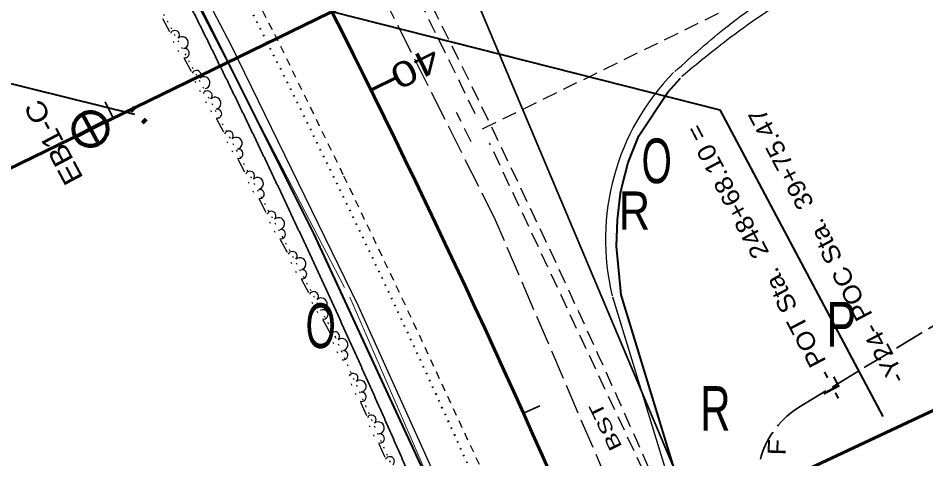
# Model space of a CAD drawing. Extents: x 2402199 to 2404507, y 568050 to 571478.
# Drawn here: x 2402420.4 to 2402674.4, y 570872 to 570995.3 of the extents above; entities that cross this region are included whole.
import ezdxf
from ezdxf.enums import TextEntityAlignment as Align

# ---------------------------------------------------------------- set-up
doc = ezdxf.new("R2010")
doc.units = 0
doc.header["$LTSCALE"] = 1.4
for name, pattern in [('DOTTED', [1.5, 0.3, -1.2]), ('LONG_DASHED', [7.5, 6, -1.5]), ('MEDIUM_DASHED', [4.5, 3, -1.5]), ('SHORT_DASHED', [2.7, 1.5, -1.2])]:
    doc.linetypes.add(name, pattern=pattern)
for name, color, linetype, lineweight in [('1', 7, 'Continuous', 35), ('11', 7, 'Continuous', 25), ('15', 7, 'DOTTED', 40), ('17', 7, 'MEDIUM_DASHED', 35), ('18', 7, 'SHORT_DASHED', 25), ('19', 7, 'Continuous', 35), ('21', 7, 'Continuous', 40), ('27', 7, 'Continuous', 80), ('28', 7, 'Continuous', 25), ('3', 7, 'Continuous', 25), ('42', 7, 'Continuous', 25), ('6', 7, 'Continuous', 35), ('62', 7, 'Continuous', 60), ('63', 7, 'Continuous', 35), ('9', 7, 'Continuous', 13)]:
    doc.layers.add(name, color=color, linetype=linetype, lineweight=lineweight)
for name, color, linetype in [('14', 7, 'Continuous'), ('2', 7, 'Continuous'), ('23', 7, 'Continuous')]:
    doc.layers.add(name, color=color, linetype=linetype)

msp = doc.modelspace()

# ---------------------------------------------------------------- linework, layer by layer
at = {"layer": '1'}
msp.add_line((2402526.719, 571052.414), (2402605.967, 570864.37), dxfattribs=at)
for points in [[(2402475.474, 570984.701), (2402475.081, 570985.499), (2402474.689, 570986.297), (2402474.296, 570987.095), (2402473.903, 570987.893), (2402473.51, 570988.691), (2402473.112, 570989.497), (2402472.718, 570990.294), (2402472.325, 570991.091), (2402471.93, 570991.889), (2402471.536, 570992.685), (2402471.141, 570993.482), (2402470.746, 570994.279), (2402470.351, 570995.076), (2402469.956, 570995.872), (2402469.56, 570996.669), (2402469.164, 570997.465), (2402468.763, 570998.27), (2402468.367, 570999.066), (2402467.97, 570999.861), (2402467.573, 571000.657), (2402467.176, 571001.453), (2402466.779, 571002.249), (2402466.381, 571003.044), (2402465.983, 571003.84), (2402465.585, 571004.634), (2402465.186, 571005.429), (2402464.788, 571006.225), (2402464.385, 571007.028), (2402463.985, 571007.823), (2402463.586, 571008.618), (2402463.186, 571009.412), (2402462.786, 571010.206), (2402462.386, 571011), (2402461.985, 571011.794), (2402461.585, 571012.589), (2402461.184, 571013.382), (2402460.783, 571014.176), (2402460.382, 571014.969), (2402459.975, 571015.772), (2402459.573, 571016.565), (2402459.171, 571017.358), (2402458.769, 571018.152), (2402458.366, 571018.944), (2402457.963, 571019.737), (2402457.56, 571020.53), (2402457.157, 571021.323), (2402456.753, 571022.115), (2402456.349, 571022.907), (2402455.945, 571023.699), (2402455.536, 571024.5), (2402455.131, 571025.293), (2402454.726, 571026.084), (2402454.321, 571026.876), (2402453.916, 571027.668), (2402453.51, 571028.459), (2402453.104, 571029.251), (2402452.698, 571030.042), (2402452.291, 571030.833), (2402451.885, 571031.624), (2402451.478, 571032.415), (2402451.071, 571033.206), (2402450.659, 571034.005), (2402450.251, 571034.796), (2402449.843, 571035.586), (2402449.435, 571036.376), (2402449.027, 571037.167), (2402448.618, 571037.956), (2402448.209, 571038.746), (2402447.8, 571039.536), (2402447.39, 571040.326), (2402446.981, 571041.116), (2402446.571, 571041.904), (2402446.157, 571042.703), (2402445.746, 571043.492)], [(2402503.828, 570925.255), (2402503.454, 570926.062), (2402503.076, 570926.878), (2402502.703, 570927.684), (2402502.328, 570928.491), (2402501.954, 570929.297), (2402501.579, 570930.103), (2402501.203, 570930.909), (2402500.828, 570931.715), (2402500.453, 570932.521), (2402500.077, 570933.327), (2402499.701, 570934.132), (2402499.325, 570934.937), (2402498.944, 570935.752), (2402498.567, 570936.557), (2402498.19, 570937.362), (2402497.812, 570938.167), (2402497.435, 570938.972), (2402497.057, 570939.777), (2402496.679, 570940.581), (2402496.3, 570941.386), (2402495.922, 570942.191), (2402495.543, 570942.994), (2402495.164, 570943.799), (2402494.785, 570944.603), (2402494.4, 570945.416), (2402494.021, 570946.22), (2402493.641, 570947.023), (2402493.26, 570947.827), (2402492.88, 570948.63), (2402492.499, 570949.434), (2402492.118, 570950.237), (2402491.736, 570951.04), (2402491.354, 570951.843), (2402490.973, 570952.646), (2402490.591, 570953.449), (2402490.204, 570954.26), (2402489.821, 570955.063), (2402489.438, 570955.865), (2402489.055, 570956.667), (2402488.672, 570957.47), (2402488.288, 570958.272), (2402487.904, 570959.074), (2402487.52, 570959.876), (2402487.136, 570960.677), (2402486.751, 570961.479), (2402486.366, 570962.28), (2402485.977, 570963.091), (2402485.591, 570963.892), (2402485.206, 570964.694), (2402484.82, 570965.494), (2402484.433, 570966.295), (2402484.047, 570967.096), (2402483.661, 570967.897), (2402483.274, 570968.697), (2402482.887, 570969.498), (2402482.499, 570970.298), (2402482.111, 570971.098), (2402481.719, 570971.907), (2402481.331, 570972.707), (2402480.942, 570973.507), (2402480.554, 570974.307), (2402480.165, 570975.106), (2402479.775, 570975.905), (2402479.386, 570976.706), (2402478.996, 570977.505), (2402478.606, 570978.304), (2402478.216, 570979.103), (2402477.826, 570979.901), (2402477.431, 570980.709), (2402477.04, 570981.508), (2402476.649, 570982.306), (2402476.257, 570983.105), (2402475.865, 570983.903), (2402475.473, 570984.702)], [(2402530.791, 570865.196), (2402530.436, 570866.011), (2402530.081, 570866.826), (2402529.726, 570867.64), (2402529.371, 570868.455), (2402529.015, 570869.269), (2402528.659, 570870.084), (2402528.303, 570870.898), (2402527.946, 570871.712), (2402527.589, 570872.526), (2402527.228, 570873.349), (2402526.871, 570874.163), (2402526.513, 570874.976), (2402526.155, 570875.791), (2402525.798, 570876.603), (2402525.439, 570877.417), (2402525.081, 570878.23), (2402524.722, 570879.043), (2402524.363, 570879.856), (2402524.004, 570880.669), (2402523.644, 570881.482), (2402523.28, 570882.304), (2402522.92, 570883.117), (2402522.56, 570883.929), (2402522.199, 570884.742), (2402521.838, 570885.554), (2402521.477, 570886.366), (2402521.115, 570887.178), (2402520.754, 570887.99), (2402520.392, 570888.802), (2402520.03, 570889.613), (2402519.668, 570890.425), (2402519.301, 570891.246), (2402518.938, 570892.057), (2402518.575, 570892.868), (2402518.212, 570893.679), (2402517.848, 570894.491), (2402517.484, 570895.302), (2402517.12, 570896.113), (2402516.755, 570896.924), (2402516.391, 570897.734), (2402516.026, 570898.544), (2402515.661, 570899.355), (2402515.291, 570900.174), (2402514.925, 570900.984), (2402514.559, 570901.794), (2402514.193, 570902.604), (2402513.827, 570903.414), (2402513.46, 570904.223), (2402513.093, 570905.034), (2402512.726, 570905.843), (2402512.358, 570906.652), (2402511.99, 570907.462), (2402511.623, 570908.271), (2402511.251, 570909.089), (2402510.882, 570909.898), (2402510.513, 570910.707), (2402510.144, 570911.515), (2402509.775, 570912.324), (2402509.405, 570913.132), (2402509.035, 570913.941), (2402508.666, 570914.749), (2402508.295, 570915.557), (2402507.925, 570916.366), (2402507.554, 570917.173), (2402507.179, 570917.99), (2402506.807, 570918.798), (2402506.436, 570919.606), (2402506.064, 570920.413), (2402505.692, 570921.22), (2402505.32, 570922.028), (2402504.947, 570922.835), (2402504.575, 570923.642), (2402504.201, 570924.449), (2402503.828, 570925.256)]]:
    msp.add_spline(points, degree=3, dxfattribs=at)
at = {"layer": '11'}
for p, q in [((2402460.745, 570995.182), (2402462.697, 570991.575)), ((2402463.703, 570988.856), (2402463.899, 570988.495)), ((2402465.07, 570986.33), (2402465.265, 570985.97)), ((2402466.798, 570984.002), (2402468.75, 570980.395)), ((2402469.757, 570977.676), (2402469.952, 570977.315)), ((2402471.123, 570975.151), (2402471.319, 570974.791)), ((2402472.815, 570971.97), (2402473.007, 570971.607)), ((2402474.161, 570969.431), (2402474.353, 570969.069)), ((2402475.866, 570967.088), (2402477.785, 570963.464)), ((2402478.766, 570960.735), (2402478.958, 570960.373)), ((2402480.11, 570958.199), (2402480.302, 570957.836)), ((2402481.816, 570955.853), (2402483.735, 570952.23)), ((2402484.717, 570949.501), (2402484.908, 570949.139)), ((2402486.061, 570946.964), (2402486.253, 570946.601)), ((2402487.767, 570944.619), (2402489.686, 570940.995)), ((2402490.668, 570938.265), (2402490.86, 570937.903)), ((2402492.012, 570935.728), (2402492.204, 570935.366)), ((2402493.717, 570933.385), (2402495.637, 570929.76)), ((2402496.618, 570927.031), (2402496.81, 570926.669)), ((2402497.962, 570924.495), (2402498.154, 570924.132)), ((2402499.668, 570922.15), (2402501.587, 570918.526)), ((2402502.568, 570915.797), (2402502.76, 570915.434)), ((2402503.913, 570913.26), (2402504.104, 570912.897)), ((2402505.619, 570910.915), (2402507.538, 570907.292)), ((2402508.407, 570904.608), (2402508.572, 570904.233)), ((2402509.557, 570901.978), (2402509.722, 570901.603)), ((2402513.502, 570892.965), (2402513.666, 570892.588)), ((2402514.653, 570890.334), (2402514.817, 570889.958)), ((2402516.18, 570887.867), (2402517.824, 570884.11)), ((2402518.599, 570881.314), (2402518.764, 570880.938)), ((2402519.75, 570878.684), (2402519.915, 570878.309)), ((2402521.277, 570876.22), (2402522.921, 570872.463))]:
    msp.add_line(p, q, dxfattribs=at)
at = {"layer": '11', "linetype": 'DOTTED'}
for points in [[(2402402.474, 571095.885), (2402413.129, 571099.725), (2402421.048, 571070.224), (2402472.559, 570975.083)], [(2402472.559, 570975.083), (2402509.097, 570906.101), (2402545.728, 570822.387)]]:
    msp.add_lwpolyline(points, dxfattribs=at)
at = {"layer": '11'}
for centre, radius, start, end in [((2402464.2, 570990.523), 1.297, 316.86691, 157.66348), ((2402466.288, 570988.389), 1.691, 284.39572, 132.46821), ((2402466.933, 570985.474), 1.297, 259.20044, 99.99701), ((2402470.253, 570979.343), 1.297, 316.86691, 157.66348), ((2402472.341, 570977.209), 1.691, 284.39572, 132.46821), ((2402473.327, 570973.633), 1.297, 316.34386, 157.14043), ((2402475.396, 570971.48), 1.691, 283.87267, 131.94516), ((2402476.015, 570968.559), 1.297, 258.67739, 99.47396), ((2402479.278, 570962.398), 1.297, 316.34386, 157.14043), ((2402481.346, 570960.245), 1.691, 283.87267, 131.94516), ((2402481.965, 570957.325), 1.297, 258.67739, 99.47396), ((2402485.228, 570951.164), 1.297, 316.34386, 157.14043), ((2402487.297, 570949.011), 1.691, 283.87267, 131.94516), ((2402487.916, 570946.09), 1.297, 258.67739, 99.47396), ((2402491.179, 570939.929), 1.297, 316.34386, 157.14043), ((2402493.248, 570937.776), 1.691, 283.87267, 131.94516), ((2402493.867, 570934.855), 1.297, 258.67739, 99.47396), ((2402497.13, 570928.694), 1.297, 316.34386, 157.14043), ((2402499.198, 570926.542), 1.691, 283.87267, 131.94516), ((2402499.817, 570923.621), 1.297, 258.67739, 99.47396), ((2402503.08, 570917.46), 1.297, 316.34386, 157.14043), ((2402505.149, 570915.307), 1.691, 283.87267, 131.94516), ((2402505.768, 570912.386), 1.297, 258.67739, 99.47396), ((2402509.031, 570906.225), 1.297, 316.34386, 157.14043), ((2402510.943, 570903.929), 1.691, 279.59664, 127.66913), ((2402511.342, 570900.97), 1.297, 254.40136, 95.19793), ((2402514.137, 570894.583), 1.297, 312.06783, 152.8644), ((2402516.039, 570892.282), 1.691, 279.59664, 127.66913), ((2402516.439, 570889.323), 1.297, 254.40136, 95.19793), ((2402519.233, 570882.936), 1.297, 312.06783, 152.8644), ((2402521.136, 570880.635), 1.691, 279.59664, 127.66913), ((2402521.535, 570877.676), 1.297, 254.40136, 95.19793), ((2402524.33, 570871.289), 1.297, 312.06783, 152.8644)]:
    msp.add_arc(centre, radius, start, end, dxfattribs=at)
at = {"layer": '15'}
msp.add_arc((2399911.332, 569690.208), 2887.133, 22.84472, 37.57762, dxfattribs=at)
at = {"layer": '17', "lineweight": 25}
for p, q in [((2402548.257, 570968.542), (2402505.556, 571055.624)), ((2402550.332, 570964.289), (2402655.74, 571015.937)), ((2402547.099, 570960.663), (2402543.057, 570968.914)), ((2402616.8, 570822.931), (2402552.299, 570960.292))]:
    msp.add_line(p, q, dxfattribs=at)
at = {"layer": '17', "linetype": 'LONG_DASHED'}
msp.add_line((2402639.183, 570886.623), (2402692.803, 570919.098), dxfattribs=at)
at = {"layer": '17', "linetype": 'Continuous', "lineweight": 60}
msp.add_line((2402707.695, 570900.235), (2402626.394, 570862.088), dxfattribs=at)
at = {"layer": '17', "lineweight": 25}
msp.add_arc((2399953.615, 569708.021), 2887.133, 22.84472, 31.18511, dxfattribs=at)
at = {"layer": '17', "linetype": 'LONG_DASHED'}
msp.add_arc((2402652.134, 570865.24), 25, 121.20094, 203.74382, dxfattribs=at)
at = {"layer": '18'}
msp.add_lwpolyline([(2402476.431, 571020.802), (2402492.105, 570990.812), (2402511.433, 570951.178), (2402527.751, 570916.956), (2402550.218, 570868.56), (2402584.143, 570790.967), (2402591.502, 570773.916)], dxfattribs=at)
at = {"layer": '19', "linetype": 'LONG_DASHED', "lineweight": 25}
msp.add_line((2402618.477, 570788.259), (2402553.966, 570938.719), dxfattribs=at)
msp.add_lwpolyline([(2402553.96, 570938.781), (2402489.547, 571067.152), (2402430.056, 571174.439), (2402385.495, 571247.202)], dxfattribs=at)
at = {"layer": '21'}
msp.add_line((2402453.011, 570968.339), (2402374.495, 570987.785), dxfattribs=at)
for points in [[(2402571.932, 570780.533), (2402538.299, 570859.007), (2402503.143, 570934.851), (2402464.804, 571011.777), (2402426.113, 571084.024), (2402384.214, 571156.832), (2402372.534, 571175.865)], [(2402605.193, 570865.012), (2402589.054, 570917.907), (2402587.809, 570931.49), (2402588.036, 570938.82), (2402588.896, 570946.33), (2402589.348, 570948.395), (2402591.028, 570954.851), (2402594.052, 570962.351), (2402602.158, 570974.597), (2402605.678, 570978.446)]]:
    msp.add_lwpolyline(points, dxfattribs=at)
at = {"layer": '27'}
for p, q in [((2402438.377, 570968.442), (2402442.831, 570960.066)), ((2402444.792, 570966.481), (2402436.416, 570962.029)), ((2402436.391, 570962.075), (2402436.416, 570962.029))]:
    msp.add_line(p, q, dxfattribs=at)
for points in [[(2402444.792, 570966.481), (2402440.604, 570964.255), (2402438.377, 570968.442), (2402438.331, 570968.417)], [(2402436.416, 570962.029), (2402440.604, 570964.255), (2402442.831, 570960.066)]]:
    msp.add_lwpolyline(points, dxfattribs=at)
msp.add_circle((2402440.604, 570964.255), 4.743, dxfattribs=at)
for start, end in [(28, 118.64427), (207.35574, 298)]:
    msp.add_arc((2402440.604, 570964.255), 4.743, start, end, dxfattribs=at)
at = {"layer": '28'}
msp.add_line((2402603.145, 570863.853), (2402586.729, 570917.175), dxfattribs=at)
msp.add_lwpolyline([(2402374.812, 571177.076), (2402399.705, 571135.603), (2402440.232, 571063.522), (2402479.967, 570987.625), (2402515.512, 570914.776), (2402552.113, 570833.795), (2402574.37, 570781.072)], dxfattribs=at)
msp.add_ellipse((2402651.713, 570933.349), major_axis=(-45.019, -49.609), ratio=0.999993, start_param=4.6772796, end_param=5.6872778, dxfattribs=at)
msp.add_spline([(2402672.797, 571021.249), (2402662.311, 571016.13), (2402638.421, 571002.609), (2402618.59, 570989.004), (2402606.097, 570978.965)], degree=3, dxfattribs=at)
at = {"layer": '3', "lineweight": 35}
msp.add_line((2402526.719, 571052.414), (2402619.911, 570831.283), dxfattribs=at)
at = {"layer": '3'}
msp.add_line((2402603.38, 570863.206), (2402586.846, 570916.911), dxfattribs=at)
msp.add_lwpolyline([(2402374.812, 571177.076), (2402399.705, 571135.603), (2402440.232, 571063.522), (2402479.967, 570987.625), (2402515.512, 570914.776), (2402552.113, 570833.795), (2402574.37, 570781.072)], dxfattribs=at)
at = {"layer": '3', "lineweight": 40}
msp.add_lwpolyline([(2402605.193, 570865.012), (2402589.054, 570917.907), (2402587.809, 570931.49), (2402588.036, 570938.82), (2402588.896, 570946.33), (2402589.348, 570948.395), (2402591.028, 570954.851), (2402594.052, 570962.351), (2402602.158, 570974.597), (2402605.678, 570978.446)], dxfattribs=at)
at = {"layer": '3'}
msp.add_ellipse((2402651.713, 570933.349), major_axis=(-45.019, -49.609), ratio=0.999993, start_param=4.6772796, end_param=5.6872778, dxfattribs=at)
at = {"layer": '42'}
msp.add_spline([(2402604.139, 570980.327), (2402619.016, 570993.164), (2402638.22, 571006.292), (2402658.089, 571017.786), (2402671.023, 571024.586)], degree=3, dxfattribs=at)
at = {"layer": '6', "lineweight": 13}
for p, q in [((2402415.453, 571105.055), (2402511.71, 570919.872)), ((2402513.131, 570917.239), (2402578.519, 570767.013))]:
    msp.add_line(p, q, dxfattribs=at)
at = {"layer": '6', "lineweight": 60}
msp.add_line((2402519.075, 570975.167), (2402526.25, 570978.706), dxfattribs=at)
at = {"layer": '6'}
for p, q in [((2402446.898, 570967.32), (2402444.709, 570971.816)), ((2402561.751, 570884.735), (2402566.308, 570886.79))]:
    msp.add_line(p, q, dxfattribs=at)
at = {"layer": '62'}
msp.add_line((2402379.217, 570934.377), (2402649.132, 571065.756), dxfattribs=at)
msp.add_arc((2399929.798, 569697.989), 2887.133, 22.84477, 31.13893, dxfattribs=at)
at = {"layer": '63', "lineweight": 40}
for p, q in [((2402508.129, 570997.124), (2402616.674, 570969.599)), ((2402616.674, 570969.599), (2402662.278, 570883.829))]:
    msp.add_line(p, q, dxfattribs=at)

# ---------------------------------------------------------------- texts
at = {"layer": '14'}
for s, height, width, p in [('R', 10.66, 0.85, (2402592.825, 570936.126)), ('P', 12.5, 0.75, (2402650.68, 570903.391)), ('R', 12.5, 0.7, (2402615.465, 570879.836))]:
    msp.add_text(s, height=height, dxfattribs=dict(at, width=width)).set_placement(p, align=Align.CENTER)
at = {"layer": '17', "width": 1.1}
msp.add_text('F', height=5, rotation=88.247, dxfattribs=at).set_placement((2402635.133, 570875.183), align=Align.CENTER)
at = {"layer": '2', "width": 1.65}
msp.add_text(':', height=7.5, rotation=45, dxfattribs=at).set_placement((2402456.039, 570966.063), align=Align.CENTER)
at = {"layer": '23', "width": 1.5}
msp.add_text('US 258    BST', height=3.691, rotation=115.818, dxfattribs=at).set_placement((2402593.5, 570867.019), align=Align.CENTER)
at = {"layer": '27', "width": 1.15}
msp.add_text('EB1-C', height=5.625, rotation=118, dxfattribs=at).set_placement((2402432.731, 570961.805), align=Align.CENTER)
at = {"layer": '63', "width": 1.35}
msp.add_text('40', height=7, rotation=206.255, dxfattribs=at).set_placement((2402530.028, 570984.448), align=Align.CENTER)
at = {"layer": '63', "width": 1.1}
for s, rotation, p in [('-Y24- POC Sta.  39+75.47', 117.733, (2402628.838, 570970.708)), ('-L- POT Sta.  248+68.10 =', 117.741, (2402611.403, 570966.22))]:
    msp.add_text(s, height=5, rotation=rotation, dxfattribs=at).set_placement(p, align=Align.RIGHT)
at = {"layer": '9', "width": 0.65}
for p in [(2402599.044, 570949.103), (2402505.015, 570902.983)]:
    msp.add_text('O', height=12.5, dxfattribs=at).set_placement(p, align=Align.CENTER)

doc.saveas('drawing.dxf')
